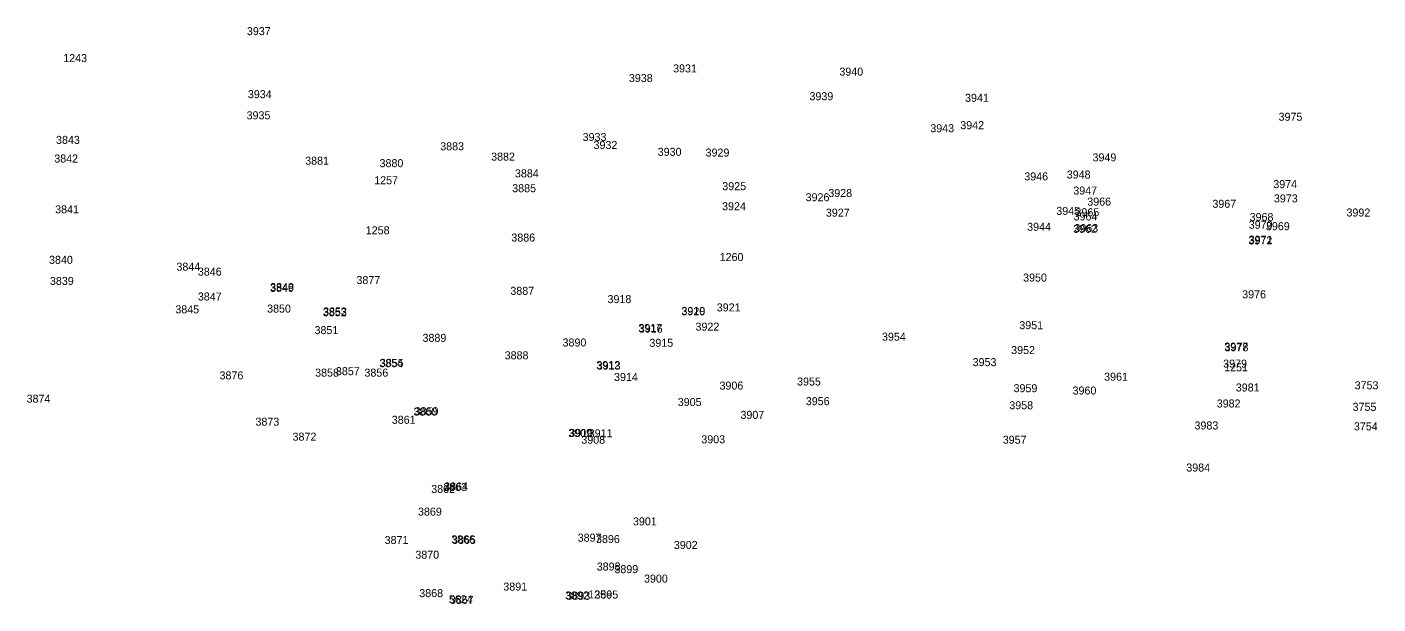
# Model space of a CAD drawing. Extents: x -740053 to -737517, y -1033516 to -1032476.
# Drawn here: x -739402.1 to -739309.2, y -1032576.8 to -1032537.1 of the extents above; entities that cross this region are included whole.
import ezdxf

# ---------------------------------------------------------------- set-up
doc = ezdxf.new("R2010")
doc.units = 0
doc.layers.add('bod-cislo', color=7, linetype='Continuous')

msp = doc.modelspace()

# ---------------------------------------------------------------- texts
at = {"layer": 'bod-cislo'}
for s, p in [('3937', (-739386.998, -1032537.693)), ('1243', (-739399.624, -1032539.545)), ('3931', (-739357.699, -1032540.253)), ('3938', (-739360.738, -1032540.913)), ('3940', (-739346.268, -1032540.473)), ('3934', (-739386.931, -1032542.023)), ('3939', (-739348.325, -1032542.163)), ('3941', (-739337.629, -1032542.273)), ('3935', (-739387.018, -1032543.473)), ('3975', (-739316.078, -1032543.573)), ('3933', (-739363.918, -1032544.963)), ('3943', (-739340.018, -1032544.363)), ('3942', (-739337.958, -1032544.153)), ('3843', (-739400.118, -1032545.163)), ('3883', (-739373.708, -1032545.603)), ('3932', (-739363.168, -1032545.513)), ('3842', (-739400.238, -1032546.443)), ('3881', (-739382.989, -1032546.593)), ('3880', (-739377.878, -1032546.763)), ('3882', (-739370.208, -1032546.313)), ('3930', (-739358.758, -1032545.983)), ('3929', (-739355.465, -1032546.033)), ('3949', (-739328.865, -1032546.363)), ('3884', (-739368.571, -1032547.463)), ('3946', (-739333.558, -1032547.673)), ('3948', (-739330.638, -1032547.543)), ('1257', (-739378.246, -1032547.937)), ('3885', (-739368.758, -1032548.483)), ('3925', (-739354.318, -1032548.343)), ('3947', (-739330.188, -1032548.643)), ('3974', (-739316.441, -1032548.203)), ('3926', (-739348.588, -1032549.103)), ('3928', (-739347.028, -1032548.813)), ('3966', (-739329.228, -1032549.403)), ('3967', (-739320.628, -1032549.553)), ('3973', (-739316.398, -1032549.183)), ('3841', (-739400.179, -1032549.933)), ('3924', (-739354.331, -1032549.723)), ('3927', (-739347.198, -1032550.163)), ('3945', (-739331.358, -1032550.043)), ('3964', (-739330.171, -1032550.423)), ('3965', (-739330.038, -1032550.133)), ('3968', (-739318.068, -1032550.463)), ('3992', (-739311.408, -1032550.153)), ('1258', (-739378.826, -1032551.373)), ('3944', (-739333.361, -1032551.133)), ('3962', (-739330.198, -1032551.273)), ('3963', (-739330.118, -1032551.223)), ('3970', (-739318.128, -1032550.993)), ('3969', (-739316.945, -1032551.093)), ('3886', (-739368.818, -1032551.873)), ('3972', (-739318.148, -1032552.073)), ('3971', (-739318.129, -1032552.013)), ('1260', (-739354.5, -1032553.212)), ('3840', (-739400.598, -1032553.403)), ('3844', (-739391.841, -1032553.873)), ('3846', (-739390.368, -1032554.213)), ('3839', (-739400.535, -1032554.853)), ('3877', (-739379.468, -1032554.793)), ('3950', (-739333.638, -1032554.623)), ('3847', (-739390.368, -1032555.923)), ('3849', (-739385.405, -1032555.333)), ('3848', (-739385.398, -1032555.273)), ('3887', (-739368.888, -1032555.533)), ('3918', (-739362.208, -1032556.103)), ('3976', (-739318.578, -1032555.773)), ('3845', (-739391.918, -1032556.803)), ('3850', (-739385.608, -1032556.753)), ('3852', (-739381.778, -1032557.003)), ('3853', (-739381.758, -1032556.953)), ('3920', (-739357.128, -1032556.943)), ('3919', (-739357.125, -1032556.913)), ('3921', (-739354.699, -1032556.673)), ('3922', (-739356.158, -1032557.993)), ('3951', (-739333.899, -1032557.893)), ('3851', (-739382.349, -1032558.233)), ('3889', (-739374.925, -1032558.763)), ('3917', (-739360.088, -1032558.083)), ('3916', (-739360.058, -1032558.133)), ('3954', (-739343.341, -1032558.683)), ('3890', (-739365.298, -1032559.083)), ('3915', (-739359.328, -1032559.103)), ('3952', (-739334.458, -1032559.603)), ('3977', (-739319.808, -1032559.363)), ('3978', (-739319.788, -1032559.413)), ('3854', (-739377.891, -1032560.503)), ('3855', (-739377.858, -1032560.483)), ('3888', (-739369.278, -1032559.963)), ('3912', (-739362.978, -1032560.633)), ('3913', (-739362.948, -1032560.673)), ('3953', (-739337.108, -1032560.433)), ('3979', (-739319.885, -1032560.533)), ('3876', (-739388.878, -1032561.343)), ('3858', (-739382.308, -1032561.153)), ('3857', (-739380.878, -1032561.053)), ('3856', (-739378.918, -1032561.153)), ('3914', (-739361.761, -1032561.453)), ('3961', (-739328.069, -1032561.433)), ('1251', (-739319.818, -1032560.788)), ('3906', (-739354.508, -1032562.043)), ('3955', (-739349.178, -1032561.763)), ('3959', (-739334.295, -1032562.223)), ('3960', (-739330.238, -1032562.383)), ('3981', (-739319.019, -1032562.173)), ('3753', (-739310.848, -1032562.023)), ('3874', (-739402.141, -1032562.943)), ('3905', (-739357.378, -1032563.173)), ('3956', (-739348.578, -1032563.113)), ('3958', (-739334.588, -1032563.393)), ('3982', (-739320.328, -1032563.273)), ('3755', (-739310.988, -1032563.503)), ('3861', (-739377.039, -1032564.393)), ('3860', (-739375.548, -1032563.833)), ('3859', (-739375.465, -1032563.803)), ('3907', (-739353.068, -1032564.053)), ('3873', (-739386.408, -1032564.523)), ('3909', (-739364.905, -1032565.303)), ('3910', (-739364.838, -1032565.293)), ('3911', (-739363.499, -1032565.323)), ('3983', (-739321.858, -1032564.783)), ('3754', (-739310.901, -1032564.843)), ('3872', (-739383.858, -1032565.553)), ('3908', (-739364.008, -1032565.763)), ('3903', (-739355.758, -1032565.733)), ('3957', (-739335.038, -1032565.763)), ('3984', (-739322.421, -1032567.673)), ('3862', (-739374.328, -1032569.143)), ('3863', (-739373.498, -1032569.013)), ('3864', (-739373.441, -1032568.973)), ('3869', (-739375.235, -1032570.703)), ('3901', (-739360.459, -1032571.373)), ('3871', (-739377.529, -1032572.653)), ('3866', (-739372.948, -1032572.603)), ('3865', (-739372.898, -1032572.643)), ('3897', (-739364.258, -1032572.493)), ('3896', (-739362.998, -1032572.583)), ('3870', (-739375.418, -1032573.663)), ('3902', (-739357.648, -1032572.993)), ('3898', (-739362.948, -1032574.473)), ('3899', (-739361.735, -1032574.653)), ('3900', (-739359.698, -1032575.303)), ('3868', (-739375.148, -1032576.303)), ('3891', (-739369.369, -1032575.853)), ('3892', (-739365.118, -1032576.463)), ('3893', (-739365.038, -1032576.483)), ('1256', (-739363.536, -1032576.39)), ('3895', (-739363.108, -1032576.403)), ('5624', (-739373.111, -1032576.723)), ('3867', (-739373.048, -1032576.763))]:
    msp.add_text(s, height=0.55, dxfattribs=at).set_placement(p)

doc.saveas('drawing.dxf')
